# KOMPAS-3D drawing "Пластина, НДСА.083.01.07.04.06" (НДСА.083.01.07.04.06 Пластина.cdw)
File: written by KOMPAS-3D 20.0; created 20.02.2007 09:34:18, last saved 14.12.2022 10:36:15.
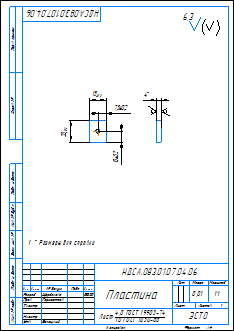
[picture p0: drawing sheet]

Sheet 1: A4, portrait

Document properties: Автор: Шубников; Организация: ЭСТО-Вакуум; Знак неуказанной шероховатости: 4; Параметр неуказанной шероховатости: 6,3; Полное имя файла: НДСА.083.01.07.04.06 Пластина.m3d; PLM_CDWXDTO: <item xmlns="http://appius.ru/pdm" xmlns:xs="http://www.w3.org/2001/XMLSchema" xmlns:xsi="http://www.w3.org/2001/XMLSchema-instance" xsi:type="item">  <element xmlns:d2p1="http://v8.1c.ru/8.1/data/enterprise/current-config" xsi:type="d2p1:CatalogRef.aps_Элемен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; Масса: 0.00912487; PDM_DOCXDTO: <item xmlns="http://appius.ru/pdm" xmlns:xs="http://www.w3.org/2001/XMLSchema" xmlns:xsi="http://www.w3.org/2001/XMLSchema-instance" xsi:type="item">  <element xmlns:d2p1="http://v8.1c.ru/8.1/data/enterprise/current-config" xsi:type="d2p1:CatalogRef.aps_Элемен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; PDM_ITEMXDTO: <item xmlns="http://appius.ru/pdm" xmlns:xs="http://www.w3.org/2001/XMLSchema" xmlns:xsi="http://www.w3.org/2001/XMLSchema-instance" xsi:type="item">  <element xmlns:d2p1="http://v8.1c.ru/8.1/data/enterprise/current-config" xsi:type="d2p1:CatalogRef.aps_Элемен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; PDM_DRAWINGXDTO: <item xmlns="http://appius.ru/pdm" xmlns:xs="http://www.w3.org/2001/XMLSchema" xmlns:xsi="http://www.w3.org/2001/XMLSchema-instance" xsi:type="item">  <element xmlns:d2p1="http://v8.1c.ru/8.1/data/enterprise/current-config" xsi:type="d2p1:CatalogRef.aps_Элемен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

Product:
- Part/product: Пластина  | designation НДСА.083.01.07.04.06
    Материал: Лист$d4,0 ГОСТ 19903-74;10 ГОСТ 1050-88$ (density 7856 kg/m3)
    Масса: 0.00912487
    additional columns: <item xmlns="http://appius.ru/pdm" xmlns:xs="http://www.w3.org/2001/XMLSchema" x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; <item xmlns="http://appius.ru/pdm" xmlns:xs="http://www.w3.org/2001/XMLSchema" x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; <item xmlns="http://appius.ru/pdm" xmlns:xs="http://www.w3.org/2001/XMLSchema" x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
    source file: НДСА.083.01.07.04.06 Пластина.cdw

Title block, sheet 1: Наименование: Пластина; designation: НДСА.083.01.07.04.06; Материал: Лист 4,0 ГОСТ 19903-74 10 ГОСТ 1050-88; Масса: 0,01; scale: 1:1; Количество листов документа: 1; organisation: ЭСТО; Форматы листов документа: A4; stored path: D:\Temp\УКРД.787.01.13.10.07 Пластина.cdw; Разработал: Щербакова; Проверил: Горностаев; Утвердил: Белецкий; Разработал, date: 09.03.2021
Table, sheet 1:
  0;Material:VDE12371B5FDD453AAD3A0896F0FE5778;Sortament:VA7372C7EC76B425B9D20DBEE7F132314^SortamentEx:VE43A138D11BD474FA4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

Views: Вид 1, Спереди, Проекционный вид 2
Referenced files in C:\Users\cherbakova\Desktop\Виноград\Новая папка (4)\: НДСА.083.01.07.04.06 Пластина.m3d
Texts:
  НДСА.083.01.07.04.06 Пластина
Dimensions and other numbers on the sheet: 15; 20; 7,5±0,2; 10±0,2; 4; 6,3; 1:1; 1; 0,01; 09.03.2021

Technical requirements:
  * Размеры для справки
